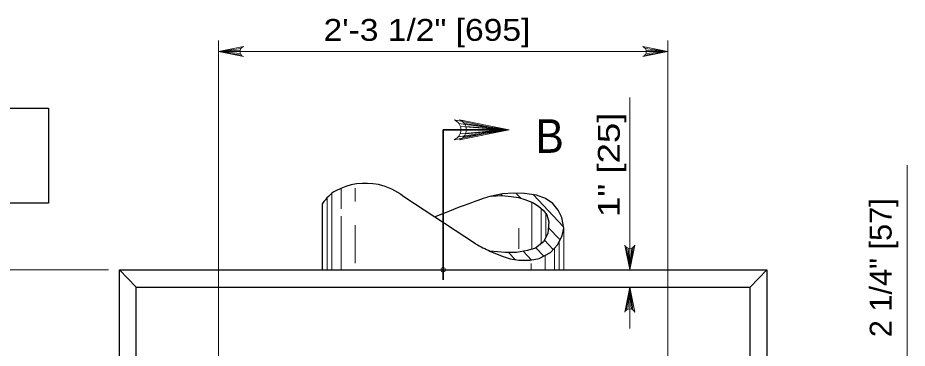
# Model space of a CAD drawing. Extents: x -410.5 to -376.5, y 1617.6 to 1661.6.
# Drawn here: x -395.5 to -389.15, y 1647.8 to 1650.16 of the extents above; entities that cross this region are included whole.
import ezdxf
from ezdxf.enums import TextEntityAlignment as Align

# ---------------------------------------------------------------- set-up
doc = ezdxf.new("R2010")
doc.units = 0
doc.header["$LTSCALE"] = 0.062
doc.header["$PDMODE"] = 32
doc.header["$PDSIZE"] = 0.031
doc.layers.add('1', color=7, linetype='Continuous', lineweight=13)

msp = doc.modelspace()

# ---------------------------------------------------------------- linework, layer by layer
at = {"layer": '1'}
for p, q in [((-394.06925, 1647.71192), (-394.06925, 1649.99775)), ((-390.85967, 1647.71192), (-390.85967, 1649.99775)), ((-393.909, 1649.94117), (-394.06925, 1649.91867)), ((-393.91442, 1649.93), (-394.06925, 1649.91867)), ((-391.01992, 1649.94117), (-390.85967, 1649.91867)), ((-391.0145, 1649.93), (-390.85967, 1649.91867)), ((-394.06925, 1649.91867), (-392.13575, 1649.91867)), ((-393.91608, 1649.91867), (-394.06925, 1649.91867)), ((-393.91325, 1649.90433), (-394.06925, 1649.91867)), ((-393.90717, 1649.89392), (-394.06925, 1649.91867)), ((-392.13575, 1649.91867), (-390.85967, 1649.91867)), ((-391.02183, 1649.89392), (-390.85967, 1649.91867)), ((-391.01567, 1649.90433), (-390.85967, 1649.91867)), ((-391.01283, 1649.91867), (-390.85967, 1649.91867)), ((-391.13075, 1648.3615), (-391.13075, 1649.59083)), ((-392.35617, 1649.31142), (-392.03183, 1649.36092)), ((-392.35233, 1649.40575), (-392.03183, 1649.36092)), ((-392.34383, 1649.33217), (-392.03183, 1649.36092)), ((-392.3415, 1649.38358), (-392.03183, 1649.36092)), ((-392.33817, 1649.36092), (-392.03183, 1649.36092)), ((-392.31683, 1649.31142), (-391.9925, 1649.36092)), ((-392.313, 1649.40575), (-391.9925, 1649.36092)), ((-392.3045, 1649.33217), (-391.9925, 1649.36092)), ((-392.30217, 1649.38358), (-391.9925, 1649.36092)), ((-392.29883, 1649.36092), (-391.9925, 1649.36092)), ((-389.148, 1647.61192), (-389.148, 1649.10725)), ((-393.2595, 1648.3615), (-393.2595, 1648.90692)), ((-393.19267, 1648.79592), (-393.19267, 1648.94417)), ((-393.0925, 1648.84867), (-393.0925, 1648.94417)), ((-391.90942, 1648.87175), (-391.94433, 1648.90892)), ((-393.29283, 1648.3615), (-393.29283, 1648.87675)), ((-392.08983, 1648.88958), (-392.09308, 1648.893)), ((-392.04525, 1648.89233), (-392.05358, 1648.90092)), ((-392.04175, 1648.89225), (-392.05067, 1648.90158)), ((-391.83, 1648.50817), (-391.83, 1648.84417)), ((-391.60458, 1648.66892), (-391.82083, 1648.89808)), ((-391.76325, 1648.54892), (-391.76325, 1648.79842)), ((-393.19267, 1648.3615), (-393.19267, 1648.74317)), ((-391.72983, 1648.59517), (-391.72983, 1648.76183)), ((-393.0925, 1648.40983), (-393.0925, 1648.67908)), ((-391.92458, 1648.51033), (-391.92458, 1648.65842)), ((-391.629, 1648.57508), (-391.71325, 1648.66425)), ((-391.60275, 1648.3615), (-391.60275, 1648.65917)), ((-391.67717, 1648.50608), (-391.741, 1648.57358)), ((-391.63608, 1648.3615), (-391.63608, 1648.56067)), ((-391.106, 1648.52367), (-391.13075, 1648.3615)), ((-392.12725, 1648.4935), (-392.12867, 1648.49525)), ((-392.113, 1648.48775), (-392.11917, 1648.49417)), ((-391.949, 1648.43417), (-391.9965, 1648.48433)), ((-391.833, 1648.43125), (-391.892, 1648.49367)), ((-391.74558, 1648.45858), (-391.80183, 1648.51817)), ((-391.73625, 1648.3615), (-391.73625, 1648.4635)), ((-391.6695, 1648.3615), (-391.6695, 1648.51467)), ((-391.15317, 1648.52175), (-391.13075, 1648.3615)), ((-391.14208, 1648.51633), (-391.13075, 1648.3615)), ((-391.11633, 1648.5175), (-391.13075, 1648.3615)), ((-391.13075, 1648.51467), (-391.13075, 1648.3615)), ((-391.83642, 1648.3615), (-391.83642, 1648.40692)), ((-394.85592, 1648.3615), (-396.20775, 1648.3615)), ((-391.1555, 1648.07442), (-391.13075, 1648.23658)), ((-391.14517, 1648.08058), (-391.13075, 1648.23658)), ((-391.13075, 1648.23658), (-391.13075, 1647.94192)), ((-391.13075, 1648.08342), (-391.13075, 1648.23658)), ((-391.11942, 1648.08175), (-391.13075, 1648.23658)), ((-391.10833, 1648.07633), (-391.13075, 1648.23658))]:
    msp.add_line(p, q, dxfattribs=at)
at = {"layer": '1', "lineweight": 35}
for p, q in [((-392.4645, 1649.36092), (-392.03183, 1649.36092)), ((-392.4645, 1648.28883), (-392.4645, 1649.36092))]:
    msp.add_line(p, q, dxfattribs=at)
at = {"layer": '1', "lineweight": 25}
for p, q in [((-392.234, 1648.54667), (-392.74575, 1648.88217)), ((-393.32617, 1648.3615), (-393.32617, 1648.83475)), ((-394.77725, 1648.3615), (-394.65925, 1648.23658)), ((-390.15167, 1648.3615), (-390.26967, 1648.23658)), ((-394.65925, 1648.23658), (-390.26967, 1648.23658)), ((-394.65925, 1647.537), (-394.65925, 1648.23658)), ((-390.26983, 1647.537), (-390.26983, 1648.23658))]:
    msp.add_line(p, q, dxfattribs=at)
at = {"layer": '1'}
for points in [[(-393.89225, 1649.88333), (-394.06925, 1649.91867), (-393.89225, 1649.95408)], [(-391.03667, 1649.88333), (-390.85967, 1649.91867), (-391.03667, 1649.95408)], [(-392.38583, 1649.29017), (-392.03183, 1649.36092), (-392.38583, 1649.43175)], [(-392.3465, 1649.29017), (-391.9925, 1649.36092), (-392.3465, 1649.43175)], [(-391.09533, 1648.5385), (-391.13075, 1648.3615), (-391.16617, 1648.5385)], [(-391.16617, 1648.05958), (-391.13075, 1648.23658), (-391.09533, 1648.05958)]]:
    msp.add_lwpolyline(points, dxfattribs=at)
at = {"layer": '1', "lineweight": 25}
msp.add_lwpolyline([(-398.78267, 1649.51433), (-395.28533, 1649.51433), (-395.28533, 1648.83658), (-398.78267, 1648.83658)], close=True, dxfattribs=at)
for points in [[(-392.13192, 1648.49558), (-392.04358, 1648.45908), (-391.98592, 1648.44092), (-391.92417, 1648.42942), (-391.84142, 1648.42975), (-391.77842, 1648.4415), (-391.69658, 1648.484), (-391.64558, 1648.54192), (-391.61333, 1648.60658), (-391.60275, 1648.65917), (-391.61567, 1648.73458), (-391.64292, 1648.7865), (-391.68025, 1648.83458), (-391.7325, 1648.871), (-391.7985, 1648.895), (-391.884, 1648.90692), (-391.96075, 1648.90942), (-392.03933, 1648.90392), (-392.1185, 1648.88783)], [(-392.13192, 1648.49558), (-392.04358, 1648.45908), (-391.98592, 1648.44092), (-391.92417, 1648.42942), (-391.84142, 1648.42975), (-391.77842, 1648.4415), (-391.69658, 1648.484), (-391.64558, 1648.54192), (-391.61333, 1648.60658), (-391.60275, 1648.65917), (-391.61567, 1648.73458), (-391.64292, 1648.7865), (-391.68025, 1648.83458), (-391.7325, 1648.871), (-391.7985, 1648.895), (-391.884, 1648.90692), (-391.96075, 1648.90942), (-392.03933, 1648.90392), (-392.1185, 1648.88783)], [(-392.1185, 1648.88783), (-392.04392, 1648.8925), (-391.97767, 1648.8855), (-391.92708, 1648.87725), (-391.88158, 1648.86342), (-391.81925, 1648.84008), (-391.78158, 1648.81392), (-391.74908, 1648.7865), (-391.72317, 1648.7535), (-391.71017, 1648.704), (-391.71658, 1648.6215), (-391.74658, 1648.56217), (-391.80492, 1648.51558), (-391.86075, 1648.499), (-391.94008, 1648.48525), (-392.02192, 1648.48392), (-392.13192, 1648.49558)], [(-392.1185, 1648.88783), (-392.04392, 1648.8925), (-391.97767, 1648.8855), (-391.92708, 1648.87725), (-391.88158, 1648.86342), (-391.81925, 1648.84008), (-391.78158, 1648.81392), (-391.74908, 1648.7865), (-391.72317, 1648.7535), (-391.71017, 1648.704), (-391.71658, 1648.6215), (-391.74658, 1648.56217), (-391.80492, 1648.51558), (-391.86075, 1648.499), (-391.94008, 1648.48525), (-392.02192, 1648.48392), (-392.13192, 1648.49558)], [(-394.77725, 1643.41433), (-394.77725, 1648.3615), (-390.15167, 1648.3615), (-390.15167, 1643.41433)]]:
    msp.add_lwpolyline(points, dxfattribs=at)
at = {"layer": '1'}
for centre, radius, start, end in [((-393.87797, 1649.91875), 0.0382, 112.08782, 247.91395), ((-391.05096, 1649.91875), 0.0382, 292.08605, 67.91218), ((-392.41446, 1649.36102), 0.0764, 292.08605, 67.91218), ((-392.37513, 1649.36102), 0.0764, 292.08605, 67.91218), ((-391.13079, 1648.55281), 0.0382, 202.08782, 337.91395), ((-391.13071, 1648.04529), 0.0382, 22.08782, 157.91395)]:
    msp.add_arc(centre, radius, start, end, dxfattribs=at)
at = {"layer": '1', "lineweight": 25}
for centre, major_axis, start_param, end_param in [((-393.01871, 1648.46974), (0, -0.5089), 2.9497702, 3.6011474), ((-393.01121, 1648.51828), (0, 0.45979), 5.6254463, 6.0881824), ((-393.08821, 1648.65916), (0, 0.30703), 0.5184487, 0.9622613)]:
    msp.add_ellipse(centre, major_axis=major_axis, ratio=0.944543, start_param=start_param, end_param=end_param, dxfattribs=at)
for points in [[(-392.1185, 1648.88783), (-392.18733, 1648.869), (-392.29775, 1648.82933), (-392.52242, 1648.73983)], [(-392.234, 1648.54667), (-392.19633, 1648.5265), (-392.16242, 1648.50967), (-392.13192, 1648.49558)]]:
    msp.add_open_spline(points, degree=3, dxfattribs=at)
at = {"layer": '1'}
msp.add_point((-392.4645, 1648.3615), dxfattribs=at)

# ---------------------------------------------------------------- texts
for s, height, width, p in [('2\'-3 1/2" [695]', 0.156, 1.15, (-393.31925, 1649.9955)), ('B', 0.24, 0.95, (-391.80525, 1649.19617))]:
    msp.add_text(s, height=height, dxfattribs=dict(at, width=width)).set_placement(p)
at = {"layer": '1', "width": 1.25}
msp.add_text('1" [25]', height=0.156, rotation=90, dxfattribs=at).set_placement((-391.20233, 1649.11071), align=Align.CENTER)
at = {"layer": '1', "width": 1.05}
msp.add_text('2 1/4" [57]', height=0.156, rotation=90, dxfattribs=at).set_placement((-389.25958, 1647.88067))

doc.saveas('drawing.dxf')
